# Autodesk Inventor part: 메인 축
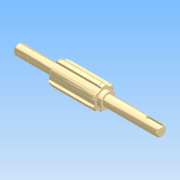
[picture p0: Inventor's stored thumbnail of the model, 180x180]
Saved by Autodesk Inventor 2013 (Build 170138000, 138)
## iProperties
Company: 한국ATC센터
Created: 2014-07
Part Number: 메인 축
Document SubType Name: 모델링
Designer: KYOUNG IL JANG
Mass: 168.566 g
Surface Area: 72.5104 cm^2
Volume: 21.4461 cm^3
Density: 7.86 g/cm^3
Material: 강철, 연강
변환 표준: STEP AP214IS
파일 이름: C:\Users\SeoGD\Desktop\?쒗뿕\硫붿씤 異?.stp
전처리기: Build: 253, Release: 2010 SP1 - Date: Wed 07/29/2009
전송 단위: 밀리미터
불확실성: 0.01
Author: KYOUNG IL JANG
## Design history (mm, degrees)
revolve "회전1" stored, may be unused: angle "d10" = 90 deg
sketch "스케치2"
  geometry: L1 (2.5, 10.712)-(2.5, 8.646); L2 (-2.5, 10.712)-(-2.5, 8.646); A1 r 9 centre (0, 0) between (2.5, 8.646) and (-2.5, 8.646) reference; A2 r 11 centre (0, 0) between (2.5, 10.712) and (-2.5, 10.712); 1 further point
  constraints: 4 end point, 4 point on circle, 2 parallel, 1 centre point, 1 coincident, 1 vertical
  dimensions: "d11" = 22 diameter of A2; "d12" = 5 distance between parallel lines of L1 L2
extrude "돌출1" join sketch "스케치2" stored distance "d13" = 10; taper "d14" = 0 deg
chamfer "모따기1" distance "d15" = 1; stored, may be unused: second distance "d16" = 2, angle "d17" = 45 deg
node "작업 평면1"
node "작업 평면2"
sketch "스케치3"
  geometry: L1 (2.5, 10.712)-(2.5, 10.198); L2 (-2.5, 10.712)-(-2.5, 10.198); A1 r 11 centre (0, 0) between (2.5, 10.712) and (-2.5, 10.712) reference; A2 r 10.5 centre (0, 0) between (2.5, 10.198) and (-2.5, 10.198); 1 further point
  constraints: 4 end point, 2 point on circle, 1 centre point, 1 coincident, 1 parallel, 1 vertical
  dimensions: "d19" = 21 diameter of A2
extrude "돌출2" cut sketch "스케치3" distance "d20" = 1.35; taper "d21" = 0 deg
node "작업 평면3"
sketch "스케치4"
  geometry: L1 (-26, -5)-(-26, 5) reference; L2 (-26, 1.5)-(-12.5, 1.5); L3 (-12.5, -1.5)-(-26, -1.5); A1 r 1.5 centre (-12.5, 0) between (-12.5, -1.5) and (-12.5, 1.5); 2 further points
  constraints: 4 end point, 2 perpendicular, 2 point on circle, 2 point on line, 2 tangent, 1 centre point, 1 horizontal alignment, 1 midpoint
  dimensions: "d25" = 3 distance between parallel lines of L3 L2; "d26" = 15 dimension on A1 L1
extrude "돌출3" cut sketch "스케치4" distance "d27" = 1.8; taper "d28" = 0 deg
chamfer "모따기2" distance "d29" = 1; stored, may be unused: second distance "d30" = 2, angle "d31" = 45 deg
node "솔리드1"
node "솔리드 본체"
node "곡면 본체"
mirror "대칭1"
pattern_circular "원형 패턴1" dims "d23" = 360 deg
sketch "스케치1"
  geometry: L1 (-69.5, 0)-(69.5, 0); L2 (69.5, 0)-(69.5, 5); L3 (69.5, 5)-(55.5, 5); L4 (55.5, 5)-(55.5, 4.8); L5 (55.5, 4.8)-(54.35, 4.8); L6 (54.35, 4.8)-(54.35, 5); L7 (54.35, 5)-(30.5, 5); L8 (30.5, 5)-(30.5, 9); L9 (30.5, 9)-(-13.5, 9); L10 (-13.5, 9)-(-13.5, 7); L11 (-13.5, 7)-(-17.5, 7); L12 (-17.5, 7)-(-17.5, 5); L13 (-17.5, 5)-(-69.5, 5); L14 (-69.5, 5)-(-69.5, 0); 2 further points
  constraints: 28 end point, 9 parallel, 4 collinear, 2 perpendicular, 1 coincident, 1 horizontal, 1 midpoint
  dimensions: "d2" = 1.15 distance between parallel lines of L6 L4; "d3" = 10 diameter of L3 L1; "d4" = 9.6 diameter of L5 L1; "d6" = 44 distance between parallel lines of L10 L8; "d7" = 4 distance between parallel lines of L12 L10; "d8" = 14 diameter of L11 L1; "d9" = 18 diameter of L9 L1; "d33" = 52 distance from line of L12.end L14; "d37" = 39 distance between parallel lines of L8 L2; "d38" = 14 distance between parallel lines of L2 L4
node "솔리드2"
other parameters: "d18" = -1.65
